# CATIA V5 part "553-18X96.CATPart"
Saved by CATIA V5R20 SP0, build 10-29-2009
Part number: 553-18X96
Definition: NONE
Nomenclature: 553-18X96
Source: Unknown
Description: 553-18X96
Bounding box of the stored display mesh (mm): x 0 to 96, y -15.5 to 15.5, z -15.5 to 15.5
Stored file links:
  C:\Users\Utente\Desktop\IO LAVORO\3D X SITO CF\X SITO\PLASTICA\553\553-18X96.CATPart
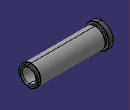
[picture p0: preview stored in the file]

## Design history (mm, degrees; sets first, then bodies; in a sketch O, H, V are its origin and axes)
Body1 "553-18X96" (main body)
  Solid1: solid without history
